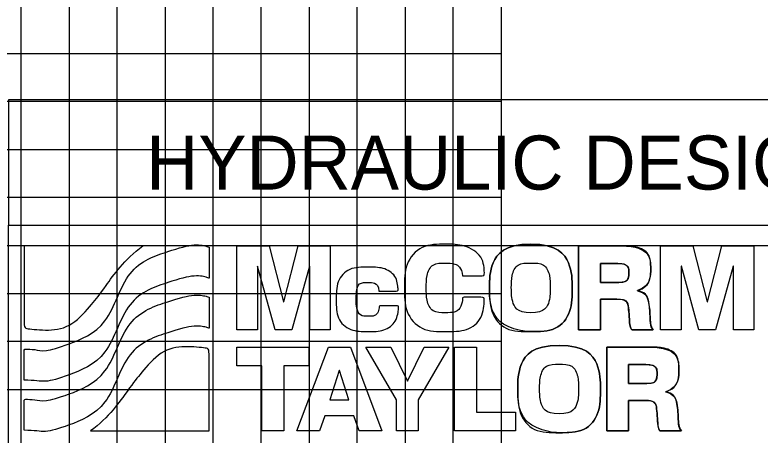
# Model space of a CAD drawing. Extents: x 1524869 to 1526553, y 501099 to 502199.
# Drawn here: x 1526435.4 to 1526513, y 501178.8 to 501222.6 of the extents above; entities that cross this region are included whole.
import ezdxf

# ---------------------------------------------------------------- set-up
doc = ezdxf.new("R2010")
doc.units = 0
for name, color, linetype in [('Prop Grid Mask', 7, 'Continuous'), ('Prop Horizontal Alignment Curve and Spiral Data', 7, 'Continuous'), ('Sheet Layout Profile Border Port 2', 7, 'Continuous'), ('Sheet Profile Grid Major CELL', 7, 'Continuous'), ('Sheet Profile Grid Middle CELL', 7, 'Continuous'), ('Sheet Profile Grid Minor CELL', 7, 'Continuous')]:
    doc.layers.add(name, color=color, linetype=linetype)

msp = doc.modelspace()

# ---------------------------------------------------------------- linework, layer by layer
at = {"layer": 'Prop Grid Mask'}
for points in [[(1526434.749, 501200.682), (1526536.08, 501200.682), (1526536.08, 501213.727), (1526434.749, 501213.727)], [(1526434.749, 501200.682), (1526536.08, 501200.682), (1526536.08, 501148.562), (1526434.749, 501148.562)]]:
    msp.add_lwpolyline(points, close=True, dxfattribs=at)
at = {"layer": 'Prop Horizontal Alignment Curve and Spiral Data'}
for p, q in [((1526458.537, 501198.515), (1526461.888, 501198.515)), ((1526458.537, 501189.785), (1526458.537, 501198.515)), ((1526461.888, 501198.515), (1526463.392, 501192.695)), ((1526463.416, 501192.695), (1526464.92, 501198.515)), ((1526464.92, 501198.515), (1526468.27, 501198.515)), ((1526468.27, 501198.515), (1526468.27, 501189.785)), ((1526502.67, 501198.515), (1526506.021, 501198.515)), ((1526502.67, 501189.785), (1526502.67, 501198.515)), ((1526506.021, 501198.515), (1526507.524, 501192.695)), ((1526507.549, 501192.695), (1526509.052, 501198.515)), ((1526509.052, 501198.515), (1526512.403, 501198.515)), ((1526512.403, 501198.515), (1526512.403, 501189.785)), ((1526460.702, 501196.412), (1526460.677, 501196.412)), ((1526460.677, 501196.412), (1526460.677, 501189.785)), ((1526462.536, 501189.785), (1526460.702, 501196.412)), ((1526466.106, 501196.412), (1526464.272, 501189.785)), ((1526466.13, 501196.412), (1526466.106, 501196.412)), ((1526466.13, 501189.785), (1526466.13, 501196.412)), ((1526504.835, 501196.412), (1526504.81, 501196.412)), ((1526504.81, 501196.412), (1526504.81, 501189.785)), ((1526506.668, 501189.785), (1526504.835, 501196.412)), ((1526510.238, 501196.412), (1526508.404, 501189.785)), ((1526510.263, 501196.412), (1526510.238, 501196.412)), ((1526510.263, 501189.785), (1526510.263, 501196.412)), ((1526500.273, 501193.868), (1526500.273, 501193.844)), ((1526463.392, 501192.695), (1526463.416, 501192.695)), ((1526507.524, 501192.695), (1526507.549, 501192.695)), ((1526460.677, 501189.785), (1526458.537, 501189.785)), ((1526464.272, 501189.785), (1526462.536, 501189.785)), ((1526468.27, 501189.785), (1526466.13, 501189.785)), ((1526501.911, 501189.785), (1526499.662, 501189.785)), ((1526504.81, 501189.785), (1526502.67, 501189.785)), ((1526508.404, 501189.785), (1526506.668, 501189.785)), ((1526512.403, 501189.785), (1526510.263, 501189.785)), ((1526458.537, 501186.021), (1526458.537, 501187.977)), ((1526458.537, 501187.977), (1526466.02, 501187.977)), ((1526464.799, 501179.247), (1526468.064, 501187.977)), ((1526466.02, 501187.977), (1526466.02, 501186.021)), ((1526468.064, 501187.977), (1526470.374, 501187.977)), ((1526470.374, 501187.977), (1526473.639, 501179.247)), ((1526475.16, 501182.499), (1526471.981, 501187.977)), ((1526471.981, 501187.977), (1526474.561, 501187.977)), ((1526474.561, 501187.977), (1526476.297, 501184.431)), ((1526476.297, 501184.431), (1526478.034, 501187.977)), ((1526480.613, 501187.977), (1526477.435, 501182.499)), ((1526478.034, 501187.977), (1526480.613, 501187.977)), ((1526481.214, 501187.977), (1526483.488, 501187.977)), ((1526481.214, 501179.247), (1526481.214, 501187.977)), ((1526483.488, 501187.977), (1526483.488, 501181.203)), ((1526461.142, 501186.021), (1526458.537, 501186.021)), ((1526461.142, 501179.247), (1526461.142, 501186.021)), ((1526466.02, 501186.021), (1526463.416, 501186.021)), ((1526463.416, 501186.021), (1526463.416, 501179.247)), ((1526469.201, 501185.556), (1526468.21, 501182.499)), ((1526469.225, 501185.556), (1526469.201, 501185.556)), ((1526470.191, 501182.499), (1526469.225, 501185.556)), ((1526503.207, 501183.33), (1526503.207, 501183.306)), ((1526468.21, 501182.499), (1526470.191, 501182.499)), ((1526475.16, 501179.247), (1526475.16, 501182.499)), ((1526477.435, 501182.499), (1526477.435, 501179.247)), ((1526467.685, 501180.811), (1526467.134, 501179.247)), ((1526470.729, 501180.811), (1526467.685, 501180.811)), ((1526471.267, 501179.247), (1526470.729, 501180.811)), ((1526483.488, 501181.203), (1526487.56, 501181.203)), ((1526487.56, 501181.203), (1526487.56, 501179.247)), ((1526463.416, 501179.247), (1526461.142, 501179.247)), ((1526467.134, 501179.247), (1526464.799, 501179.247)), ((1526473.639, 501179.247), (1526471.267, 501179.247)), ((1526477.435, 501179.247), (1526475.16, 501179.247)), ((1526487.56, 501179.247), (1526481.214, 501179.247)), ((1526504.845, 501179.247), (1526502.596, 501179.247))]:
    msp.add_line(p, q, dxfattribs=at)
for points in [[(1526458.537, 501198.515), (1526461.888, 501198.515), (1526463.392, 501192.695), (1526463.416, 501192.695), (1526464.92, 501198.515), (1526468.27, 501198.515), (1526468.27, 501189.785), (1526466.13, 501189.785), (1526466.13, 501196.412), (1526466.106, 501196.412), (1526464.272, 501189.785), (1526462.536, 501189.785), (1526460.702, 501196.412), (1526460.677, 501196.412), (1526460.677, 501189.785), (1526458.537, 501189.785), (1526458.537, 501198.515)], [(1526498.133, 501192.964), (1526496.409, 501192.964), (1526496.409, 501189.785), (1526494.135, 501189.785), (1526494.135, 501198.515), (1526498.586, 501198.515)], [(1526502.67, 501198.515), (1526506.021, 501198.515), (1526507.524, 501192.695), (1526507.549, 501192.695), (1526509.052, 501198.515), (1526512.403, 501198.515), (1526512.403, 501189.785), (1526510.263, 501189.785), (1526510.263, 501196.412), (1526510.238, 501196.412), (1526508.404, 501189.785), (1526506.668, 501189.785), (1526504.835, 501196.412), (1526504.81, 501196.412), (1526504.81, 501189.785), (1526502.67, 501189.785), (1526502.67, 501198.515)], [(1526498.219, 501196.693), (1526496.409, 501196.693), (1526496.409, 501194.724), (1526498.317, 501194.724)], [(1526466.02, 501186.021), (1526463.416, 501186.021), (1526463.416, 501179.247), (1526461.142, 501179.247), (1526461.142, 501186.021), (1526458.537, 501186.021), (1526458.537, 501187.977), (1526466.02, 501187.977), (1526466.02, 501186.021)], [(1526468.064, 501187.977), (1526470.374, 501187.977), (1526473.639, 501179.247), (1526471.267, 501179.247), (1526470.729, 501180.811), (1526467.685, 501180.811), (1526467.134, 501179.247), (1526464.799, 501179.247), (1526468.064, 501187.977)], [(1526477.435, 501182.499), (1526477.435, 501179.247), (1526475.16, 501179.247), (1526475.16, 501182.499), (1526471.981, 501187.977), (1526474.561, 501187.977), (1526476.297, 501184.431), (1526478.034, 501187.977), (1526480.613, 501187.977), (1526477.435, 501182.499)], [(1526481.214, 501187.977), (1526483.488, 501187.977), (1526483.488, 501181.203), (1526487.56, 501181.203), (1526487.56, 501179.247), (1526481.214, 501179.247), (1526481.214, 501187.977)], [(1526501.067, 501182.426), (1526499.343, 501182.426), (1526499.343, 501179.247), (1526497.069, 501179.247), (1526497.069, 501187.977), (1526501.519, 501187.977)], [(1526468.21, 501182.499), (1526470.191, 501182.499), (1526469.225, 501185.556), (1526469.201, 501185.556), (1526468.21, 501182.499)], [(1526501.153, 501186.155), (1526499.343, 501186.155), (1526499.343, 501184.187), (1526501.251, 501184.187)]]:
    msp.add_lwpolyline(points, dxfattribs=at)
for points in [[(1526436.372, 501184.534), (1526437.494, 501184.534), (1526438.503, 501184.236), (1526440.63, 501184.902), (1526445.328, 501186.711), (1526446.854, 501193.206), (1526451.716, 501194.85), (1526454.277, 501195.577), (1526455.654, 501195.168), (1526455.654, 501195.168), (1526455.654, 501195.168), (1526455.654, 501198.398), (1526455.654, 501198.398), (1526455.654, 501198.398), (1526454.277, 501198.807), (1526451.716, 501198.08), (1526446.854, 501196.436), (1526445.328, 501189.94), (1526440.63, 501188.132), (1526438.503, 501187.466), (1526437.494, 501187.764), (1526436.372, 501187.764), (1526436.372, 501187.764), (1526436.372, 501184.534), (1526436.372, 501184.534)], [(1526436.372, 501184.534), (1526437.494, 501184.534), (1526438.503, 501184.236), (1526440.63, 501184.902), (1526445.328, 501186.711), (1526446.854, 501193.206), (1526451.716, 501194.85), (1526454.277, 501195.577), (1526455.654, 501195.168), (1526455.654, 501195.168), (1526455.654, 501195.168), (1526455.654, 501198.398), (1526455.654, 501198.398), (1526455.654, 501198.398), (1526454.277, 501198.807), (1526451.716, 501198.08), (1526446.854, 501196.436), (1526445.328, 501189.94), (1526440.63, 501188.132), (1526438.503, 501187.466), (1526437.494, 501187.764), (1526436.372, 501187.764), (1526436.372, 501187.764), (1526436.372, 501184.534), (1526436.372, 501184.534)], [(1526482.052, 501195.397), (1526481.929, 501196.277), (1526481.245, 501196.742), (1526480.291, 501196.742), (1526478.824, 501196.742), (1526478.261, 501195.446), (1526478.261, 501194.15), (1526478.261, 501192.854), (1526478.824, 501191.558), (1526480.291, 501191.558), (1526481.355, 501191.558), (1526481.966, 501192.169), (1526482.052, 501193.171), (1526482.052, 501193.171), (1526484.326, 501193.171), (1526484.326, 501193.171), (1526484.203, 501190.921), (1526482.553, 501189.602), (1526480.339, 501189.602), (1526477.699, 501189.602), (1526475.987, 501191.619), (1526475.987, 501194.15), (1526475.987, 501196.68), (1526477.699, 501198.698), (1526480.339, 501198.698), (1526482.223, 501198.698), (1526484.265, 501197.5), (1526484.326, 501195.397), (1526484.326, 501195.397), (1526482.052, 501195.397), (1526482.052, 501195.397)], [(1526482.052, 501195.397), (1526481.929, 501196.277), (1526481.245, 501196.742), (1526480.291, 501196.742), (1526478.824, 501196.742), (1526478.261, 501195.446), (1526478.261, 501194.15), (1526478.261, 501192.854), (1526478.824, 501191.558), (1526480.291, 501191.558), (1526481.355, 501191.558), (1526481.966, 501192.169), (1526482.052, 501193.171), (1526482.052, 501193.171), (1526484.326, 501193.171), (1526484.326, 501193.171), (1526484.203, 501190.921), (1526482.553, 501189.602), (1526480.339, 501189.602), (1526477.699, 501189.602), (1526475.987, 501191.619), (1526475.987, 501194.15), (1526475.987, 501196.68), (1526477.699, 501198.698), (1526480.339, 501198.698), (1526482.223, 501198.698), (1526484.265, 501197.5), (1526484.326, 501195.397), (1526484.326, 501195.397), (1526482.052, 501195.397), (1526482.052, 501195.397)], [(1526488.094, 501189.711), (1526486.008, 501190.164), (1526484.852, 501191.965), (1526484.852, 501194.15), (1526484.852, 501196.68), (1526486.404, 501198.698), (1526489.156, 501198.698)], [(1526489.156, 501198.698), (1526491.907, 501198.698), (1526493.46, 501196.68), (1526493.46, 501194.15), (1526493.46, 501191.619), (1526491.907, 501189.602), (1526489.156, 501189.602), (1526486.404, 501189.602), (1526484.852, 501191.619), (1526484.852, 501194.15), (1526484.852, 501196.68), (1526486.404, 501198.698), (1526489.156, 501198.698)], [(1526489.156, 501198.698), (1526491.907, 501198.698), (1526493.46, 501196.68), (1526493.46, 501194.15), (1526493.46, 501191.619), (1526491.907, 501189.602), (1526489.156, 501189.602), (1526488.779, 501189.602), (1526488.425, 501189.639), (1526488.094, 501189.711)], [(1526448.729, 501198.528), (1526446.824, 501197.124), (1526444.486, 501193.737), (1526443.601, 501192.679), (1526441.412, 501190.065), (1526438.919, 501189.64), (1526436.372, 501189.944), (1526436.372, 501189.944), (1526436.372, 501198.528), (1526436.372, 501198.528), (1526436.372, 501198.528), (1526448.729, 501198.528), (1526448.729, 501198.528)], [(1526448.729, 501198.528), (1526446.824, 501197.124), (1526444.486, 501193.737), (1526443.601, 501192.679), (1526441.412, 501190.065), (1526438.919, 501189.64), (1526436.372, 501189.944), (1526436.372, 501189.944), (1526436.372, 501198.528), (1526436.372, 501198.528), (1526436.372, 501198.528), (1526448.729, 501198.528), (1526448.729, 501198.528)], [(1526494.135, 501198.515), (1526494.135, 501198.515), (1526498.586, 501198.515), (1526498.586, 501198.515), (1526500.127, 501198.515), (1526501.642, 501197.818), (1526501.642, 501196.057), (1526501.642, 501195.116), (1526501.191, 501194.223), (1526500.273, 501193.868), (1526500.273, 501193.868), (1526500.273, 501193.844), (1526500.273, 501193.844), (1526501.202, 501193.624), (1526501.471, 501192.585), (1526501.545, 501191.753), (1526501.57, 501191.386), (1526501.606, 501190.103), (1526501.911, 501189.785), (1526501.911, 501189.785), (1526499.662, 501189.785), (1526499.662, 501189.785), (1526499.466, 501190.078), (1526499.429, 501190.934), (1526499.405, 501191.178), (1526499.344, 501192.059), (1526499.197, 501192.964), (1526498.133, 501192.964), (1526498.133, 501192.964), (1526496.409, 501192.964), (1526496.409, 501192.964), (1526496.409, 501192.964), (1526496.409, 501189.785), (1526496.409, 501189.785), (1526496.409, 501189.785), (1526494.135, 501189.785), (1526494.135, 501189.785), (1526494.135, 501189.785), (1526494.135, 501198.515), (1526494.135, 501198.515)], [(1526498.586, 501198.515), (1526500.127, 501198.515), (1526501.642, 501197.818), (1526501.642, 501196.057), (1526501.642, 501195.116), (1526501.191, 501194.223), (1526500.273, 501193.868)], [(1526489.156, 501191.558), (1526490.623, 501191.558), (1526491.186, 501192.854), (1526491.186, 501194.15), (1526491.186, 501195.446), (1526490.623, 501196.742), (1526489.156, 501196.742), (1526487.688, 501196.742), (1526487.126, 501195.446), (1526487.126, 501194.15), (1526487.126, 501192.854), (1526487.688, 501191.558), (1526489.156, 501191.558)], [(1526489.156, 501191.558), (1526490.623, 501191.558), (1526491.186, 501192.854), (1526491.186, 501194.15), (1526491.186, 501195.446), (1526490.623, 501196.742), (1526489.156, 501196.742), (1526487.688, 501196.742), (1526487.126, 501195.446), (1526487.126, 501194.15), (1526487.126, 501192.854), (1526487.688, 501191.558), (1526489.156, 501191.558)], [(1526496.409, 501194.724), (1526496.409, 501194.724), (1526498.317, 501194.724), (1526498.317, 501194.724), (1526499.001, 501194.724), (1526499.368, 501195.091), (1526499.368, 501195.751), (1526499.368, 501196.4), (1526498.855, 501196.693), (1526498.219, 501196.693), (1526498.219, 501196.693), (1526496.409, 501196.693), (1526496.409, 501196.693), (1526496.409, 501196.693), (1526496.409, 501194.724), (1526496.409, 501194.724)], [(1526498.317, 501194.724), (1526499.001, 501194.724), (1526499.368, 501195.091), (1526499.368, 501195.751), (1526499.368, 501196.4), (1526498.855, 501196.693), (1526498.219, 501196.693)], [(1526473.33, 501193.807), (1526473.318, 501194.345), (1526472.841, 501194.724), (1526472.315, 501194.724), (1526471.154, 501194.724), (1526470.97, 501193.734), (1526470.97, 501192.854), (1526470.97, 501192.034), (1526471.324, 501191.191), (1526472.205, 501191.191), (1526472.926, 501191.191), (1526473.293, 501191.606), (1526473.391, 501192.279), (1526473.391, 501192.279), (1526475.408, 501192.279), (1526475.408, 501192.279), (1526475.225, 501190.579), (1526473.905, 501189.602), (1526472.217, 501189.602), (1526470.31, 501189.602), (1526468.891, 501190.909), (1526468.891, 501192.854), (1526468.891, 501194.871), (1526470.175, 501196.314), (1526472.217, 501196.314), (1526473.794, 501196.314), (1526475.201, 501195.483), (1526475.347, 501193.807), (1526475.347, 501193.807), (1526473.33, 501193.807), (1526473.33, 501193.807)], [(1526473.33, 501193.807), (1526473.318, 501194.345), (1526472.841, 501194.724), (1526472.315, 501194.724), (1526471.154, 501194.724), (1526470.97, 501193.734), (1526470.97, 501192.854), (1526470.97, 501192.034), (1526471.324, 501191.191), (1526472.205, 501191.191), (1526472.926, 501191.191), (1526473.293, 501191.606), (1526473.391, 501192.279), (1526473.391, 501192.279), (1526475.408, 501192.279), (1526475.408, 501192.279), (1526475.225, 501190.579), (1526473.905, 501189.602), (1526472.217, 501189.602), (1526470.31, 501189.602), (1526468.891, 501190.909), (1526468.891, 501192.854), (1526468.891, 501194.871), (1526470.175, 501196.314), (1526472.217, 501196.314), (1526473.794, 501196.314), (1526475.201, 501195.483), (1526475.347, 501193.807), (1526475.347, 501193.807), (1526473.33, 501193.807), (1526473.33, 501193.807)], [(1526436.372, 501179.313), (1526437.494, 501179.313), (1526438.503, 501179.014), (1526440.63, 501179.681), (1526445.328, 501181.489), (1526446.854, 501187.985), (1526451.716, 501189.628), (1526454.277, 501190.356), (1526455.654, 501189.947), (1526455.654, 501189.947), (1526455.654, 501189.947), (1526455.654, 501193.177), (1526455.654, 501193.177), (1526455.654, 501193.177), (1526454.277, 501193.586), (1526451.716, 501192.858), (1526446.854, 501191.215), (1526445.328, 501184.718), (1526440.63, 501182.91), (1526438.503, 501182.244), (1526437.494, 501182.543), (1526436.372, 501182.543), (1526436.372, 501182.543), (1526436.372, 501179.313), (1526436.372, 501179.313)], [(1526436.372, 501179.313), (1526437.494, 501179.313), (1526438.503, 501179.014), (1526440.63, 501179.681), (1526445.328, 501181.489), (1526446.854, 501187.985), (1526451.716, 501189.628), (1526454.277, 501190.356), (1526455.654, 501189.947), (1526455.654, 501189.947), (1526455.654, 501189.947), (1526455.654, 501193.177), (1526455.654, 501193.177), (1526455.654, 501193.177), (1526454.277, 501193.586), (1526451.716, 501192.858), (1526446.854, 501191.215), (1526445.328, 501184.718), (1526440.63, 501182.91), (1526438.503, 501182.244), (1526437.494, 501182.543), (1526436.372, 501182.543), (1526436.372, 501182.543), (1526436.372, 501179.313), (1526436.372, 501179.313)], [(1526500.273, 501193.844), (1526501.202, 501193.624), (1526501.471, 501192.585), (1526501.545, 501191.753), (1526501.57, 501191.386), (1526501.606, 501190.103), (1526501.911, 501189.785)], [(1526499.662, 501189.785), (1526499.466, 501190.078), (1526499.429, 501190.934), (1526499.405, 501191.178), (1526499.344, 501192.059), (1526499.197, 501192.964), (1526498.133, 501192.964)], [(1526443.296, 501179.246), (1526445.201, 501180.65), (1526447.538, 501184.038), (1526448.424, 501185.095), (1526450.612, 501187.71), (1526453.105, 501188.134), (1526455.653, 501187.83), (1526455.653, 501187.83), (1526455.653, 501179.246), (1526455.653, 501179.246), (1526455.653, 501179.246), (1526443.296, 501179.246), (1526443.296, 501179.246)], [(1526443.296, 501179.246), (1526445.201, 501180.65), (1526447.538, 501184.038), (1526448.424, 501185.095), (1526450.612, 501187.71), (1526453.105, 501188.134), (1526455.653, 501187.83), (1526455.653, 501187.83), (1526455.653, 501179.246), (1526455.653, 501179.246), (1526455.653, 501179.246), (1526443.296, 501179.246), (1526443.296, 501179.246)], [(1526491.039, 501179.173), (1526488.954, 501179.625), (1526487.797, 501181.427), (1526487.797, 501183.612), (1526487.797, 501186.143), (1526489.35, 501188.16), (1526492.101, 501188.16)], [(1526492.101, 501188.16), (1526494.852, 501188.16), (1526496.405, 501186.143), (1526496.405, 501183.612), (1526496.405, 501181.08), (1526494.852, 501179.063), (1526492.101, 501179.063), (1526489.35, 501179.063), (1526487.797, 501181.08), (1526487.797, 501183.612), (1526487.797, 501186.143), (1526489.35, 501188.16), (1526492.101, 501188.16)], [(1526492.101, 501188.16), (1526494.852, 501188.16), (1526496.405, 501186.143), (1526496.405, 501183.612), (1526496.405, 501181.08), (1526494.852, 501179.063), (1526492.101, 501179.063), (1526491.725, 501179.063), (1526491.37, 501179.101), (1526491.039, 501179.173)], [(1526497.069, 501187.977), (1526497.069, 501187.977), (1526501.519, 501187.977), (1526501.519, 501187.977), (1526503.06, 501187.977), (1526504.576, 501187.28), (1526504.576, 501185.519), (1526504.576, 501184.578), (1526504.124, 501183.685), (1526503.207, 501183.33), (1526503.207, 501183.33), (1526503.207, 501183.306), (1526503.207, 501183.306), (1526504.136, 501183.086), (1526504.405, 501182.047), (1526504.478, 501181.215), (1526504.503, 501180.848), (1526504.54, 501179.565), (1526504.845, 501179.247), (1526504.845, 501179.247), (1526502.596, 501179.247), (1526502.596, 501179.247), (1526502.4, 501179.54), (1526502.363, 501180.396), (1526502.339, 501180.641), (1526502.278, 501181.521), (1526502.131, 501182.426), (1526501.067, 501182.426), (1526501.067, 501182.426), (1526499.343, 501182.426), (1526499.343, 501182.426), (1526499.343, 501182.426), (1526499.343, 501179.247), (1526499.343, 501179.247), (1526499.343, 501179.247), (1526497.069, 501179.247), (1526497.069, 501179.247), (1526497.069, 501179.247), (1526497.069, 501187.977), (1526497.069, 501187.977)], [(1526501.519, 501187.977), (1526503.06, 501187.977), (1526504.576, 501187.28), (1526504.576, 501185.519), (1526504.576, 501184.578), (1526504.124, 501183.685), (1526503.207, 501183.33)], [(1526492.101, 501181.02), (1526493.569, 501181.02), (1526494.131, 501182.316), (1526494.131, 501183.612), (1526494.131, 501184.908), (1526493.569, 501186.204), (1526492.101, 501186.204), (1526490.634, 501186.204), (1526490.072, 501184.908), (1526490.072, 501183.612), (1526490.072, 501182.316), (1526490.634, 501181.02), (1526492.101, 501181.02)], [(1526492.101, 501181.02), (1526493.569, 501181.02), (1526494.131, 501182.316), (1526494.131, 501183.612), (1526494.131, 501184.908), (1526493.569, 501186.204), (1526492.101, 501186.204), (1526490.634, 501186.204), (1526490.072, 501184.908), (1526490.072, 501183.612), (1526490.072, 501182.316), (1526490.634, 501181.02), (1526492.101, 501181.02)], [(1526499.343, 501184.187), (1526499.343, 501184.187), (1526501.251, 501184.187), (1526501.251, 501184.187), (1526501.935, 501184.187), (1526502.302, 501184.553), (1526502.302, 501185.213), (1526502.302, 501185.862), (1526501.789, 501186.155), (1526501.153, 501186.155), (1526501.153, 501186.155), (1526499.343, 501186.155), (1526499.343, 501186.155), (1526499.343, 501186.155), (1526499.343, 501184.187), (1526499.343, 501184.187)], [(1526501.251, 501184.187), (1526501.935, 501184.187), (1526502.302, 501184.553), (1526502.302, 501185.213), (1526502.302, 501185.862), (1526501.789, 501186.155), (1526501.153, 501186.155)], [(1526503.207, 501183.306), (1526504.136, 501183.086), (1526504.405, 501182.047), (1526504.478, 501181.215), (1526504.503, 501180.848), (1526504.54, 501179.565), (1526504.845, 501179.247)], [(1526502.596, 501179.247), (1526502.4, 501179.54), (1526502.363, 501180.396), (1526502.339, 501180.641), (1526502.278, 501181.521), (1526502.131, 501182.426), (1526501.067, 501182.426)]]:
    msp.add_open_spline(points, degree=3, dxfattribs=at)
at = {"layer": 'Sheet Layout Profile Border Port 2'}
msp.add_lwpolyline([(1525086.08, 501648.562), (1526486.08, 501648.562), (1526486.08, 501148.562), (1525086.08, 501148.562)], close=True, dxfattribs=at)
at = {"layer": 'Sheet Profile Grid Major CELL'}
for points in [[(1525986.08, 501148.562), (1526036.08, 501148.562), (1526036.08, 501648.562), (1526086.08, 501648.562), (1526086.08, 501148.562), (1526136.08, 501148.562), (1526136.08, 501648.562), (1526186.08, 501648.562), (1526186.08, 501148.562), (1526236.08, 501148.562), (1526236.08, 501648.562), (1526286.08, 501648.562), (1526286.08, 501148.562), (1526336.08, 501148.562), (1526336.08, 501648.562), (1526386.08, 501648.562), (1526386.08, 501148.562), (1526436.08, 501148.562), (1526436.08, 501148.562), (1526436.08, 501648.562), (1526486.08, 501648.562), (1526486.08, 501148.562)], [(1526536.08, 501248.562), (1525036.08, 501248.562), (1525036.08, 501248.562), (1525036.08, 501198.562), (1526536.08, 501198.562)]]:
    msp.add_lwpolyline(points, dxfattribs=at)
at = {"layer": 'Sheet Profile Grid Middle CELL'}
msp.add_lwpolyline([(1526011.08, 501148.562), (1526061.08, 501148.562), (1526061.08, 501648.562), (1526111.08, 501648.562), (1526111.08, 501148.562), (1526161.08, 501148.562), (1526161.08, 501648.562), (1526211.08, 501648.562), (1526211.08, 501148.562), (1526261.08, 501148.562), (1526261.08, 501648.562), (1526311.08, 501648.562), (1526311.08, 501148.562), (1526361.08, 501148.562), (1526361.08, 501648.562), (1526411.08, 501648.562), (1526411.08, 501148.562), (1526461.08, 501148.562), (1526461.08, 501648.562)], dxfattribs=at)
at = {"layer": 'Sheet Profile Grid Minor CELL'}
for p, q in [((1525086.08, 501218.562), (1526486.08, 501218.562)), ((1526486.08, 501213.562), (1525086.08, 501213.562)), ((1525086.08, 501208.562), (1526486.08, 501208.562)), ((1526486.08, 501203.562), (1525086.08, 501203.562)), ((1525086.08, 501193.562), (1526486.08, 501193.562)), ((1526486.08, 501188.562), (1525086.08, 501188.562)), ((1525086.08, 501183.562), (1526486.08, 501183.562))]:
    msp.add_line(p, q, dxfattribs=at)
for points in [[(1526441.08, 501648.562), (1526441.08, 501148.562), (1526446.08, 501148.562), (1526446.08, 501648.562)], [(1526451.08, 501648.562), (1526451.08, 501148.562), (1526456.08, 501148.562), (1526456.08, 501648.562)], [(1526466.08, 501648.562), (1526466.08, 501148.562), (1526471.08, 501148.562), (1526471.08, 501648.562)], [(1526476.08, 501648.562), (1526476.08, 501148.562), (1526481.08, 501148.562), (1526481.08, 501648.562)]]:
    msp.add_lwpolyline(points, dxfattribs=at)

# ---------------------------------------------------------------- texts
at = {"layer": 'Prop Horizontal Alignment Curve and Spiral Data'}
msp.add_text('HYDRAULIC DESIGN', height=5.625, rotation=360, dxfattribs=at).set_placement((1526449.092, 501204.392))

doc.saveas('drawing.dxf')
